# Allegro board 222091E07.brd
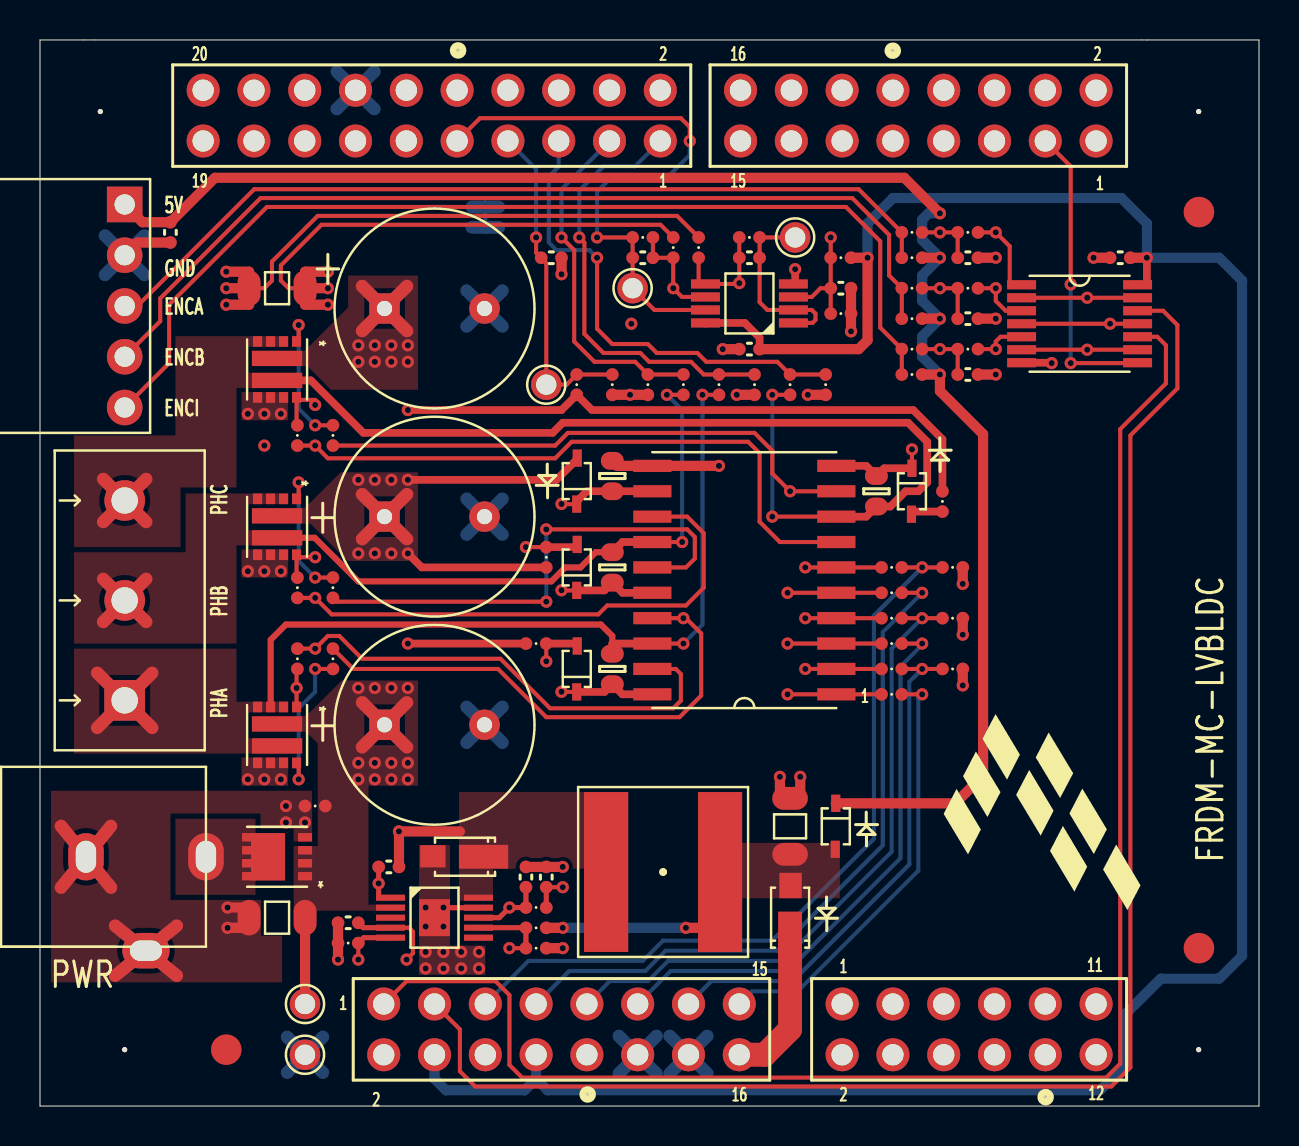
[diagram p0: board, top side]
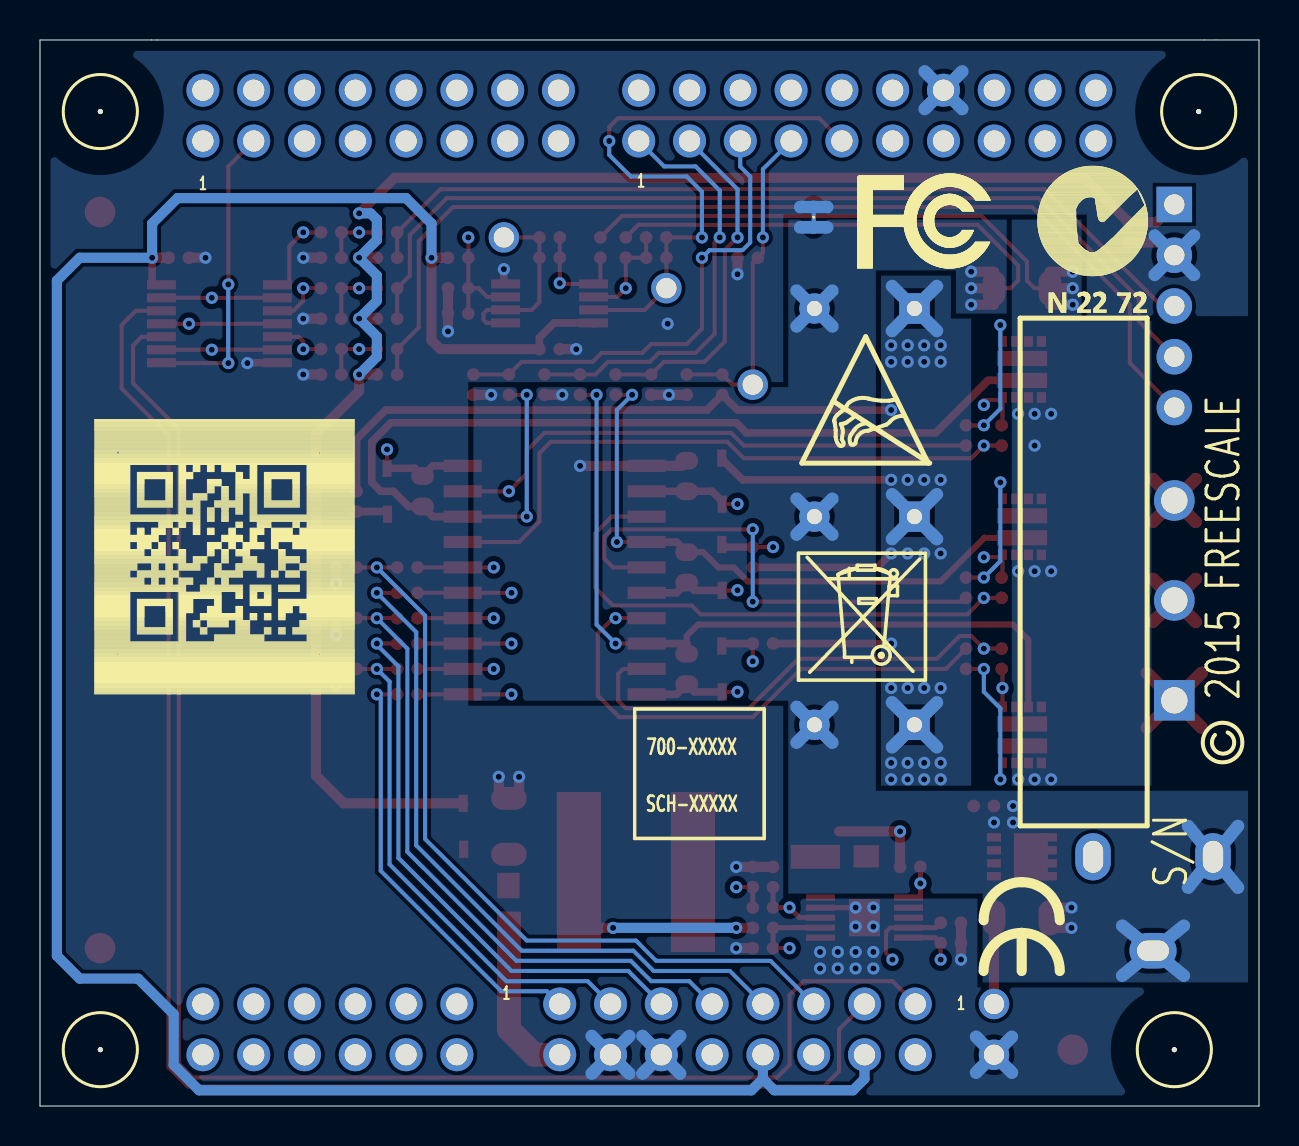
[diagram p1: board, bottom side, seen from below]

Outline 60.96 x 53.34 mm; copper layers: TOP, BOTTOM. Coordinates in mm from the lower left corner of the outline.
Outline path: 0,53.34 60.96,53.34 60.96,0 0,0 0,53.34

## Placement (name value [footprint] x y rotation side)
C1  220uF  [CAPRD_10X12P5MM]  19.73 19.08 0 top
C2  220uF  [CAPRD_10X12P5MM]  19.73 29.49 0 top
C3  220uF  [CAPRD_10X12P5MM]  19.73 39.9 0 top
C4  0.1uF  [CC0603_OV]  28.62 21.87 90 top
C5  0.1uF  [CC0603_OV]  28.62 26.95 90 top
C6  0.1uF  [CC0603_OV]  41.83 30.76 270 top
C10  0.1uF  [CC0603_OV]  28.62 31.52 90 top
C16  0.1uF  [CC0402_25]  40.05 40.92 0 top
C17  0.1uF  [CC0402_25]  25.57 42.44 0 top
C18  0.1uF  [CC0402_25]  35.48 37.87 180 top
C22  0.01uF  [CC0402_25]  35.48 42.44 180 top
C23  0.01uF  [CC0402_25]  30.14 42.44 180 top
C24  100pF  [CC0402_25]  46.4 42.44 0 top
C25  100pF  [CC0402_25]  46.4 39.4 0 top
C26  100pF  [CC0402_25]  46.4 36.6 0 top
C27  0.1uF  [CC0402_25]  6.52 43.71 270 top
C29  0.1uF  [CC0402_25]  54.02 42.44 180 top
C35  0.1uF  [CC0402_25]  17.44 11.96 0 top
C36  6.8nF  [CC0402_25]  15.41 9.17 180 top
C37  24pF  [CC0402_25]  24.3 11.46 90 top
C38  620pF  [CC0402_25]  25.32 11.46 90 top
C39  4.7uF  [CC1206_OV]  11.86 9.42 180 top
C40  47uF  [CC1206_OV]  37.51 14 90 top
D1  1N914  [SODFL2513X100N]  43.61 30.76 270 top
D2  1N914  [SODFL2513X100N]  26.84 26.95 90 top
D3  1N914  [SODFL2513X100N]  26.84 21.87 90 top
D4  1N914  [SODFL2513X100N]  26.84 31.27 90 top
D5  DFLS1100  [SODFL3718X100N]  21.25 12.47 180 top
D6  1N914  [SODFL2513X100N]  39.8 14 270 top
D7  DFLS1100  [SODFL3718X100N]  37.51 9.42 90 top
J1  SSQ-108-03-G-D  [SAMTEC_SSQ-108-03-G-D]  52.81 48.29 180 top
J2  SSQ-110-03-G-D  [SAMTEC_SSQ-110-03-G-D]  31.02 48.29 180 top
J3  SSQ-108-03-G-D  [SAMTEC_SSQ-108-03-G-D]  17.19 5.11 0 top
J4  SSQ-106-03-G-D  [SAMTEC_SSQ-106-03-G-D]  40.11 5.11 0 top
J6  PJ-102AH  [CON_PJ-102AH]  8.3 12.47 0 top
J7  KRM03  [CON_KRM03]  4.24 25.3 270 top
J8  22-05-3051  [CON_22-05-3051]  4.24 45.11 90 top
L1  47uH  [IND_SRN8040]  31.16 11.71 0 top
NOREF  -  []  55.04 9.8 90 top
NOREF#2  -  [unnamed#2]  57.96 44.73 0 top
NOREF#3  -  []  -43.63 -145.92 0 top
NOREF#4  -  []  182.19 53.34 0 top
NOREF#5  -  []  58.85 25.04 0 top
NOREF#6  -  []  -27.3 -36.7 0 top
NOREF#7  -  []  0 53.34 0 top
NOREF#8  -  []  -418.71 -339.88 0 top
NOREF#9  -  []  -392.68 185.27 0 top
NOREF#10  -  []  60.96 0 90 top
NOREF#11  -  [unnamed#2]  9.32 2.82 0 top
NOREF#12  -  []  4.24 2.82 0 top
NOREF#13  -  [unnamed#2]  57.96 7.9 0 top
NOREF#14  -  []  -15.5 14.61 180 bottom
NOREF#15  -  [unnamed#2]  3.02 49.76 180 bottom
NOREF#16  -  []  5.59 14.02 90 bottom
NOREF#17  -  [unnamed#2]  57.94 49.76 180 bottom
NOREF#18  -  []  11.87 9.36 180 bottom
NOREF#19  -  []  51.87 27.86 180 bottom
NOREF#20  -  [unnamed#2]  57.94 2.82 180 bottom
NOREF#21  -  []  23.03 21.31 180 bottom
NOREF#22  -  [unnamed#2]  4.24 2.82 180 bottom
NOREF#23  -  []  26.59 21.79 90 bottom
NOREF#24  -  []  1.95 18.31 90 bottom
Q1  FDMC8030  [POWER33-10]  11.86 18.57 270 top
Q2  FDMC8030  [POWER33-10]  11.86 28.98 270 top
Q3  FDMC8030  [POWER33-10]  11.86 36.86 270 top
Q4  FDMC6679AZ  [POWER33-8]  11.86 12.47 180 top
R1  10  [RC0402_25]  45.13 30.25 270 top
R2  10  [RC0402_25]  25.32 27.46 90 top
R3  10K  [RC0402_25]  13.76 15.01 180 top
R4  10  [RC0402_25]  12.87 22.38 270 top
R5  10  [RC0402_25]  14.65 25.93 90 top
R6  10  [RC0402_25]  14.65 33.55 90 top
R7  10  [RC0402_25]  24.81 23.14 0 top
R8  10  [RC0402_25]  14.65 22.38 270 top
R9  10  [RC0402_25]  12.87 25.93 90 top
R10  1K  [RC0402_25]  42.59 20.6 180 top
R11  1K  [RC0402_25]  42.59 21.87 180 top
R12  10  [RC0402_25]  12.87 33.55 90 top
R16  1K  [RC0402_25]  42.59 23.14 180 top
R17  1K  [RC0402_25]  42.59 24.41 180 top
R18  1K  [RC0402_25]  42.59 25.68 180 top
R19  1K  [RC0402_25]  42.59 26.95 180 top
R32  10K  [RC0402_25]  40.05 42.44 180 top
R33  10.7K  [RC0402_25]  26.84 36.09 90 top
R34  10K  [RC0402_25]  40.05 39.65 0 top
R35  3K  [RC0402_25]  28.62 36.09 270 top
R36  0.010  [RC1206_OV]  11.86 40.92 0 top
R37  1K  [RC0402_25]  32.94 42.95 270 top
R38  1K  [RC0402_25]  31.67 42.95 270 top
R39  20K  [RC0402_25]  30.14 43.46 180 top
R40  20K  [RC0402_25]  35.48 43.46 180 top
R41  10.7K  [RC0402_25]  32.18 36.09 90 top
R42  3K  [RC0402_25]  30.4 36.09 270 top
R43  3K  [RC0402_25]  35.73 36.09 270 top
R44  10.7K  [RC0402_25]  33.95 36.09 90 top
R45  3K  [RC0402_25]  39.29 36.09 270 top
R46  10.7K  [RC0402_25]  37.51 36.09 90 top
R47  2K  [RC0402_25]  46.4 43.71 0 top
R48  1K  [RC0402_25]  43.61 42.44 180 top
R49  100  [RC0402_25]  43.61 43.71 0 top
R50  2K  [RC0402_25]  46.4 40.92 0 top
R51  1K  [RC0402_25]  43.61 39.4 180 top
R52  100  [RC0402_25]  43.61 40.92 0 top
R53  1K  [RC0402_25]  43.61 36.6 180 top
R54  2K  [RC0402_25]  46.4 37.87 0 top
R55  100  [RC0402_25]  43.61 37.87 0 top
R56  84.5K  [RC0402_25]  15.41 8.15 180 top
R57  59K  [RC0402_25]  24.81 8.92 180 top
R58  10K  [RC0402_25]  24.81 7.9 0 top
R59  150K  [RC0402_25]  24.81 9.93 0 top
R70  4.7K  [RC0402_25]  45.64 21.87 0 top
R71  4.7K  [RC0402_25]  45.64 24.41 0 top
R72  4.7K  [RC0402_25]  45.64 26.95 0 top
SH1  0  [RC0402_25_CT]  22.27 44.48 270 bottom
TP4  TP  [TP_TH_040]  37.76 43.46 0 top
TP5  TP  [TP_TH_040]  25.32 36.09 0 top
TP6  TP  [TP_TH_040]  29.64 40.92 0 top
TP7  TP  [TP_TH_040]  13.25 5.11 0 top
TP8  TP  [TP_TH_040]  13.25 2.57 0 top
U1  FAN7888  [SOIC127P1032X265-20N]  35.22 26.31 180 top
U2  FAN4852  [SOP65P490X110-8N]  35.48 40.16 180 top
U6  74LVX14  [SOP65P640X120-14N]  51.99 39.14 0 top
U7  TPS54060  [SOP50P490X110-11N]  19.73 9.42 0 top

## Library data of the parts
C1-C3 = CAP_POL
C4-C6 C10 C16-C18 C22-C27 C29 C35-C40 = CAP_NP
D1-D4 D6 = 1N914BWS
D5 D7 = DFLS1100
J1 J3 = CONN_2x8
J2 = CONN_2x10
J4 = CONN_2x6
J6 = PJ-102AH
J7 = KRM03
J8 = CON5
L1 = SRN8040
Q1-Q3 = FDMC8030
Q4 = FDMC6679AZ
R1-R12 R16-R19 R32-R59 R70-R72 = RES
SH1 = SH_RES
TP4-TP8 = TP
U1 = FAN7888
U2 = FAN4852
U6 = 74LVX14
U7 = TPS54060

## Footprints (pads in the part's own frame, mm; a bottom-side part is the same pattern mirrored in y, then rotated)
CAPRD_10X12P5MM
  rect 1.524x1.524 hole 0.762: 1(-2.5,0)
  round 1.524 hole 0.762: 2(2.5,0)
CC0402_25
  round 0.635 smd: 1(-0.508,0) 2(0.508,0)
CC0603_OV
  oval 0.889x1.143 smd: 1(-0.762,0) 2(0.762,0)
CC1206_OV
  oval 1.143x1.778 smd: 1(-1.4,0) 2(1.4,0)
CON_22-05-3051
  rect 1.778x1.778 hole 1.016: 1(0,0)
  round 1.778 hole 1.016: 2(-2.54,0) 3(-5.08,0) 4(-7.62,0) 5(-10.16,0)
CON_KRM03
  rect 2.032x2.032 hole 1.321: 1(5,0)
  round 2.032 hole 1.321: 2(0,0) 3(-5,0)
CON_PJ-102AH
  oval 1.778x2.362 hole 1.016x1.6: 1(0,0) 2(-6,0)
  oval 2.362x1.778 hole 1.6x1.016: 3(-3,-4.7)
IND_SRN8040
  rect 2.21x8.001 smd: 1(-2.85,0) 2(2.85,0)
POWER33-8
  rect 1.7x2.37 smd: (0.45,0)
  rect 0.7x0.42 smd: 1(-1.4,0.975) 2(-1.4,0.325) 3(-1.4,-0.325) 4(-1.4,-0.975) 5(1.4,-0.975) 6(1.4,-0.325) 7(1.4,0.325) 8(1.4,0.975)
POWER33-10
  rect 0.533x0.457 smd: 1(-1.4,0.975) 2(-1.4,0.325) 3(-1.4,-0.325) 4(-1.4,-0.975) 5(1.4,-0.975) 6(1.4,-0.325) 7(1.4,0.325) 8(1.4,0.975)
  rect 0.762x2.515 smd: 9(-0.55,0) 10(0.55,0)
RC0402_25
  round 0.635 smd: 1(-0.508,0) 2(0.508,0)
RC0402_25_CT
  round 0.635 smd: 1(-0.508,0) 2(0.508,0)
RC1206_OV
  oval 1.143x1.778 smd: 1(-1.4,0) 2(1.4,0)
SAMTEC_SSQ-106-03-G-D
  round 1.651 hole 1.067: 1(0,0) 2(0,-2.54) 3(2.54,0) 4(2.54,-2.54) 5(5.08,0) 6(5.08,-2.54) 7(7.62,0) 8(7.62,-2.54) 9(10.16,0) 10(10.16,-2.54) 11(12.7,0) 12(12.7,-2.54)
SAMTEC_SSQ-108-03-G-D
  round 1.651 hole 1.067: 1(0,0) 2(0,-2.54) 3(2.54,0) 4(2.54,-2.54) 5(5.08,0) 6(5.08,-2.54) 7(7.62,0) 8(7.62,-2.54) 9(10.16,0) 10(10.16,-2.54) 11(12.7,0) 12(12.7,-2.54) 13(15.24,0) 14(15.24,-2.54) 15(17.78,0) 16(17.78,-2.54)
SAMTEC_SSQ-110-03-G-D
  round 1.651 hole 1.067: 1(0,0) 2(0,-2.54) 3(2.54,0) 4(2.54,-2.54) 5(5.08,0) 6(5.08,-2.54) 7(7.62,0) 8(7.62,-2.54) 9(10.16,0) 10(10.16,-2.54) 11(12.7,0) 12(12.7,-2.54) 13(15.24,0) 14(15.24,-2.54) 15(17.78,0) 16(17.78,-2.54) 17(20.32,0) 18(20.32,-2.54) 19(22.86,0) 20(22.86,-2.54)
SODFL2513X100N
  rect 0.864x0.457 smd: A(1.15,-0.025) C(-1.15,0)
SODFL3718X100N
  rect 1.27x1.118 smd: A(1.61,-0.025)
  rect 2.464x1.194 smd: C(-0.93,0)
SOIC127P1032X265-20N
  rect 1.905x0.61 smd: 1(-4.6,5.715) 2(-4.6,4.445) 3(-4.6,3.175) 4(-4.6,1.905) 5(-4.6,0.635) 6(-4.6,-0.635) 7(-4.6,-1.905) 8(-4.6,-3.175) 9(-4.6,-4.445) 10(-4.6,-5.715) 11(4.6,-5.715) 12(4.6,-4.445) 13(4.6,-3.175) 14(4.6,-1.905) 15(4.6,-0.635) 16(4.6,0.635) 17(4.6,1.905) 18(4.6,3.175) 19(4.6,4.445) 20(4.6,5.715)
SOP50P490X110-11N
  rect 1.448x0.305 smd: 1(-2.2,1) 2(-2.2,0.5) 3(-2.2,0) 4(-2.2,-0.5) 5(-2.2,-1) 6(2.2,-1) 7(2.2,-0.5) 8(2.2,0) 9(2.2,0.5) 10(2.2,1)
  rect 1.549x1.854 smd: 11(0,0)
SOP65P490X110-8N
  rect 1.448x0.457 smd: 1(-2.2,0.975) 2(-2.2,0.325) 3(-2.2,-0.325) 4(-2.2,-0.975) 5(2.2,-0.975) 6(2.2,-0.325) 7(2.2,0.325) 8(2.2,0.975)
SOP65P640X120-14N
  rect 1.448x0.457 smd: 1(-2.9,1.95) 2(-2.9,1.3) 3(-2.9,0.65) 4(-2.9,0) 5(-2.9,-0.65) 6(-2.9,-1.3) 7(-2.9,-1.95) 8(2.9,-1.95) 9(2.9,-1.3) 10(2.9,-0.65) 11(2.9,0) 12(2.9,0.65) 13(2.9,1.3) 14(2.9,1.95)
TP_TH_040
  round 1.524 hole 1.016: 1(0,0)
unnamed#2
  round 1.524 smd: (0,0)

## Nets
3V3: C18.1 C29.1 J3.4(B2) J3.8(B4) R32.1 U2.8(V+) U6.14(VCC)
5V: C27.1 D6.C J8.1 R48.1 R51.1 R53.1
5V5: C40.1 D6.A D7.A L1.2 R57.1
5V_OUT: D7.C J3.16(B8)
GND: C16.2 C17.2 C18.2 C24.2 C25.2 C26.2 C27.2 C29.2 C36.2 C37.2 C38.2 C40.2 D5.A J2.14(B7) J3.12(B6) J3.14(B7) J8.2 R34.2 R56.2 R58.2 R70.2 R71.2 R72.2 SH1.1 TP8.1(TP) U2.4(-IN) U6.7(GND) U7.9(GND) U7.11(PAD)
GNDM: C1.2(MINUS) C2.2(MINUS) C3.2(MINUS) C10.2 C39.2 J6.2 J6.3 Q4.4(G) R3.2 R35.2 R36.2 R38.1 R42.2 R43.2 R45.2 SH1.2 U1.11(GND)
ADC_MID: C22.1 R40.1 TP4.1(TP) U2.1(OUTA) U2.2(-INA)
BEMF_A: J2.1(A1) R43.1 R44.2
BEMF_B: J2.3(A2) R41.2 R42.1
BEMF_C: J2.5(A3) R45.1 R46.2
CS_DCB_H: Q1.5(S13) Q1.6(S12) Q1.7(S11) Q2.5(S13) Q2.6(S12) Q2.7(S11) Q3.5(S13) Q3.6(S12) Q3.7(S11) R36.1 R37.1
CUR_DCB: C23.2 J2.9(A5) R39.2 TP6.1(TP) U2.7(OUTB)
ENC_A: J3.3(A2) U6.12(Y)
ENC_B: J3.1(A1) U6.10(Y)
ENC_I: J1.3(A2) U6.8(Y)
HOA: R4.1 U1.19(HO1)
HOB: R5.1 U1.15(HO2)
HOC: R6.1 U1.9(HO3)
LOA: R8.1 U1.17(LO1)
LOB: R9.1 U1.13(LO2)
LOC: R12.1 U1.7(LO3)
PH_A: C4.2 J7.1 Q1.2(S11) Q1.3(S12) Q1.4(S13) Q1.10(D2) R44.1 U1.18(VS1)
PH_B: C5.2 J7.2 Q2.2(S11) Q2.3(S12) Q2.4(S13) Q2.10(D2) R41.1 U1.14(VS2)
PH_C: C6.2 J7.3 Q3.2(S11) Q3.3(S12) Q3.4(S13) Q3.10(D2) R46.1 U1.8(VS3)
PWM_AB: J3.13(A7) R11.1 R70.1
PWM_AT: J3.15(A8) R10.1
PWM_BB: J3.9(A5) R17.1 R71.1
PWM_BT: J3.11(A6) R16.1
PWM_CB: J3.5(A3) R19.1 R72.1
PWM_CT: J3.7(A4) R18.1
VM: C1.1(PLUS) C2.1(PLUS) C3.1(PLUS) C39.1 D4.A Q1.9(D2) Q2.9(D2) Q3.9(D2) Q4.1(S1) Q4.2(S2) Q4.3(S3) R1.1 R2.1 R3.1 R7.1 R33.1 TP7.1(TP) U7.2(VIN)
VOLT_DCB: C17.1 J2.7(A4) R33.2 R35.1 TP5.1(TP)
N24033468: C4.1 D3.C U1.20(VB1)
N24033594: C5.1 D2.C U1.16(VB2)
N24033653: C6.1 D1.C U1.10(VB3)
N24035180: D1.A R1.2
N24035201: D2.A R2.2
N24035206: D3.A R7.2
N24035227: Q1.1(G2) R4.2
N24035245: Q1.8(G2) R8.2
N24035263: Q2.1(G2) R5.2
N24035281: Q2.8(G2) R9.2
N24035326: Q3.8(G2) R12.2
N24035327: Q3.1(G2) R6.2
N24037051: C10.1 D4.C U1.12(VDD)
N24055425: C16.1 R32.2 R34.1 U2.3(+INA)
N24056935: R18.2 U1.5(HIN3)
N24056936: R16.2 U1.3(HIN2)
N24056937: R10.2 U1.1(HIN1)
N24056938: R19.2 U1.6(LIN3)
N24056939: R17.2 U1.4(LIN2)
N24056940: R11.2 U1.2(LIN1)
N24071789: C22.2 R37.2 R40.2 U2.5(+INB)
N24071791: C23.1 R38.2 R39.1 U2.6(-INB)
N24077170: C24.1 R47.1 R49.2
N24077180: J8.3 R48.2 R49.1
N24077887: J8.4 R51.2 R52.1
N24077889: C25.1 R50.1 R52.2
N24077981: J8.5 R53.2 R55.1
N24077985: C26.1 R54.1 R55.2
N24130653: R47.2 U6.1(A)
N24130655: R50.2 U6.3(A)
N24130657: R54.2 U6.5(A)
N24130659: U6.6(Y) U6.9(A)
N24130661: U6.4(Y) U6.11(A)
N24130663: U6.2(Y) U6.13(A)
N24141092: J6.1 Q4.5(D1) Q4.6(D2) Q4.7(D3) Q4.8(D4)
N24147614: C35.1 U7.1(BOOT)
N24147651: C35.2 D5.C L1.1 U7.10(PH)
N24147683: R57.2 R58.1 U7.7(VSEN)
N24147707: R56.1 U7.5(RT)
N24147711: C36.1 U7.4(SS)
N24147721: C37.1 R59.1 U7.8(COMP)
N24147753: C38.1 R59.2

Pads without a net: J1 1 2 4 5 6 7 8 9 10 11 12 13 14 15 16; J2 2 4 6 8 10 11 12 13 15 16 17 18 19 20; J3 2 6 10; J4 1 2 3 4 5 6 7 8 9 10 11 12; U7 3 6

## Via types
v1: diameter 0.61, hole 0.305, TOP to BOTTOM, 160 vias

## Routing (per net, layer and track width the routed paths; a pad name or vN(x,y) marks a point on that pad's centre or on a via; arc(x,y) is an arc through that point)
3V3: length 122.1
  TOP w0.381: U6.14 55.35,41.09 v1(55.35,42.44) ; 33.28,39.14 U2.8 35.25,39.18 35.99,38.44 C18.1
  TOP w0.508: C18.1 40.94,37.87 41.38,38.32 v1(41.38,42.44) R32.1 ; C29.1 v1(55.35,42.44)
  BOTTOM w0.508: 24.81,1.36 J3.8 ; 24.81,1.36 24.24,0.79 20.3,0.79 19.73,1.36 J3.4 ; 24.81,1.36 25.38,0.79 53,0.79 54.27,2.06 54.27,4.6 56.05,6.38 58.97,6.38 60.12,7.52 60.12,41.3 58.97,42.44 v1(55.35,42.44) 55.35,44.16 54.08,45.43 42.65,45.43 41.38,44.16 v1(41.38,42.44)
5V: length 85
  TOP w0.508: v1(45,44.67) 43.22,46.44 8.74,46.44 C27.1 5.12,44.22 J8.1 ; R51.1 v1(45,39.4) ; R53.1 v1(45,36.6) 45,35.78 47.16,33.62 47.16,16.54 45.77,15.15 D6.C ; R48.1 v1(45,42.44)
  BOTTOM w0.508: v1(45,36.6) 44.11,37.49 44.11,38.51 v1(45,39.4) 44.11,40.28 44.11,41.55 v1(45,42.44) 44.11,43.33 44.11,44.35 44.43,44.67 v1(45,44.67)
5V5: length 11.5
  TOP w0.508: L1.2 34.01,8.92 v1(32.3,8.92) ; R57.1 v1(26.14,8.92)
  BOTTOM w0.508: v1(26.14,8.92) v1(32.3,8.92)
5V_OUT: length 7.7
  TOP w1.194: J3.16 36.24,2.57 37.51,3.84 D7.C
GND: length 52
  TOP w0.254: U7.9 20.18,9.92 v1(20.17,9.93)
  TOP w0.381: U6.7 50.57,37.19 v1(50.59,37.17) ; v1(37.76,41.87) 37.76,41.13 U2.4
  TOP w0.508: C26.2 v1(47.8,36.6) ; C16.2 R34.2 v1(40.56,38.76) ; C36.2 R56.2 v1(14.9,7.33) ; v1(38.02,16.47) 38.02,15.4 C40.2 37,15.4 v1(37,16.47) ; C25.2 v1(47.8,39.4) ; v1(26.14,11.96) C38.2 C37.2 ; C18.2 v1(34.14,37.87) ; R71.2 v1(46.15,23.58) ; C27.2 4.87,43.21 J8.2 ; C17.2 v1(26.08,41.62) ; R58.2 v1(26.14,7.9) ; C24.2 v1(47.8,42.44) ; R70.2 v1(46.15,21.04) ; R72.2 v1(46.15,26.12) ; C29.2 v1(52.69,42.44)
  BOTTOM w0.635: J3.14 33.37,3.5 ; J3.14 31.49,3.5 ; J3.14 31.49,1.63 ; J3.14 33.37,1.63 ; 14.84,51.76 J2.14 ; J2.14 14.84,49.89 ; J2.14 16.72,49.89 ; J2.14 16.72,51.76 ; J3.12 30.83,3.5 ; J3.12 30.83,1.63 ; J3.12 28.95,1.63 ; J3.12 28.95,3.5 ; TP8.1 14.14,1.67 ; TP8.1 12.36,1.67 ; TP8.1 14.14,3.46 ; TP8.1 12.36,3.46 ; 3.25,43.55 J8.2 ; J8.2 5.22,43.55 ; J8.2 5.22,41.59 ; J8.2 3.25,41.59 ; 22.94,44.98 SH1.1 21.6,44.98
  vias: v1(19.28,9.93) v1(19.28,8.98) v1(19.28,7.71) v1(19.28,6.88) v1(20.17,8.98) v1(20.17,7.71) v1(20.17,6.88) v1(21.06,7.71) v1(21.06,6.88) v1(21.95,7.71) v1(21.95,6.88) v1(29.57,39.14)
GNDM: length 88.2
  TOP w0.203: R38.1 31.03,44.09 14.08,44.09 12.05,42.06 12.05,41.3 12.43,40.92 R36.2
  TOP w0.508: R36.2 13.26,41.74 v1(14.4,41.74) ; R36.2 13.26,40.09 v1(14.4,40.09) ; R36.2 v1(14.4,40.92) ; v1(33.95,32.03) U1.11 28.87,32.03 C10.2 ; v1(9.38,9.93) 10.46,9.93 C39.2 10.46,8.92 v1(9.38,8.92) ; R35.2 v1(29.51,35.59) R42.2 ; R43.2 v1(34.84,35.59) ; R45.2 v1(38.4,35.59)
  TOP w0.635: 1.05,14.01 J6.2 ; J6.2 3.54,10.93 ; J6.2 1.05,10.93 ; J6.2 3.54,14.01 ; J6.3 6.84,6.53 ; J6.3 3.76,6.53 ; J6.3 3.76,9.02 ; J6.3 6.84,9.02
  BOTTOM w0.635: J6.2 3.54,14.01 ; J6.2 1.05,14.01 ; J6.2 3.54,10.93 ; J6.2 1.05,10.93 ; C3.2 23.12,40.8 ; C3.2 21.34,40.8 ; C3.2 21.34,39.01 ; C3.2 23.12,39.01 ; C1.2 23.12,18.18 ; C1.2 23.12,19.97 ; C1.2 21.34,18.18 ; C1.2 21.34,19.97 ; 21.34,30.38 C2.2 ; C2.2 23.12,28.6 ; C2.2 21.34,28.6 ; C2.2 23.12,30.38 ; 22.94,43.97 SH1.2 21.6,43.97 ; 3.76,6.53 J6.3 ; J6.3 3.76,9.02 ; J6.3 6.84,6.53 ; J6.3 6.84,9.02
  vias: v1(12.3,15.01) v1(12.3,14.19) v1(13.25,14.19)
ADC_MID: length 9.5
  TOP w0.203: U2.1 38.63,39.18 38.78,39.33 38.78,39.65 38.6,39.83 U2.2 36.37,39.83 35.99,40.22 C22.1 R40.1 TP4.1
BEMF_A: length 21.7
  TOP w0.203: v1(26.97,43.46) 27.22,43.21 27.22,38.63 28.17,37.68 30.02,37.68 30.46,37.24 32.56,37.24 33.19,36.6 R44.2 R43.1
  BOTTOM w0.203: v1(26.97,43.46) 26.97,45.81 28.17,47.02 29.75,47.02 J2.1
BEMF_B: length 17.4
  TOP w0.203: v1(26.08,43.46) 26.71,42.82 26.71,38.25 27.73,37.24 29.76,37.24 R42.1 R41.2
  BOTTOM w0.203: J2.3 28.48,48.27 26.08,45.87 v1(26.08,43.46)
BEMF_C: length 23.9
  TOP w0.203: R45.1 R46.2 36.87,37.24 33.32,37.24 32.87,37.68 30.84,37.68 30.4,38.13 28.62,38.13 27.86,38.89 v1(27.86,42.44)
  BOTTOM w0.203: J2.5 25.94,47 25.44,46.51 25.44,43.21 25.83,42.82 27.48,42.82 v1(27.86,42.44)
CS_DCB_H: length 30.1
  TOP w0.203: R36.1 11.22,40.92 11.6,41.3 11.6,42.25 13.89,44.54 31.86,44.54 R37.1
  TOP w0.508: v1(9.32,41.74) 10.46,41.74 R36.1 ; R36.1 v1(9.32,40.92) ; R36.1 10.46,40.09 v1(9.32,40.09)
  vias: v1(10.39,34.63) v1(10.39,26.76) v1(10.39,16.34) v1(11.22,34.63) v1(11.22,33.05) v1(11.22,26.76) v1(11.22,16.34) v1(12.05,34.63) v1(12.05,26.76) v1(12.05,16.34)
CUR_DCB: length 29.8
  TOP w0.203: v1(32.49,48.29) 32.49,48.98 32.05,49.43 22,49.43 J2.9 ; v1(27.86,43.46) R39.2 C23.2 TP6.1 30.72,39.83 U2.7
  BOTTOM w0.203: v1(27.86,43.46) 27.86,45.75 28.62,46.51 31.41,46.51 32.49,47.59 v1(32.49,48.29)
ENC_A: length 78.5
  TOP w0.203: J3.3 21,3.84 21,1.74 21.76,0.98 53.57,0.98 54.53,1.93 54.53,33.55 56.88,35.9 56.88,39.08 56.16,39.79 U6.12
ENC_B: length 80.1
  TOP w0.203: U6.10 55.88,38.49 56.31,38.06 56.31,36.16 54.02,33.87 54.02,2.12 53.32,1.42 24.11,1.42 23.48,2.06 23.48,5.55 22.78,6.25 18.33,6.25 J3.1
ENC_I: length 15
  TOP w0.203: v1(51.54,41.11) 51.54,47.02 J1.3 ; v1(51.54,37.17) 54.87,37.17 U6.8
  BOTTOM w0.203: v1(51.54,41.11) v1(51.54,37.17)
HOA: length 24
  TOP w0.203: U1.19 31.79,21.87 32.05,21.62 32.05,20.28 31.67,19.9 25.51,19.9 23.03,22.38 16.11,22.38 14.97,23.52 14.4,23.52 v1(13.76,22.89) R4.1
HOB: length 25.3
  TOP w0.203: v1(25.32,25.23) 14.84,25.23 R5.1 ; v1(25.32,28.85) 32.37,28.85 32.75,28.47 32.75,27.39 32.3,26.95 U1.15
  BOTTOM w0.203: v1(25.32,28.85) v1(25.32,25.23)
HOC: length 27.3
  TOP w0.203: R6.1 25.76,33.05 26.4,33.68 35.73,33.68 36.62,32.79 36.62,31.65 v1(37.51,30.76) U1.9
LOA: length 26.2
  TOP w0.203: U1.17 v1(32.18,24.41) 32.3,24.41 33.06,23.65 33.06,20.54 31.98,19.46 25.32,19.46 22.9,21.87 15.67,21.87 R8.1
LOB: length 26.9
  TOP w0.203: U1.13 32.37,29.49 33.19,28.66 33.19,25.93 32.3,25.04 28.37,25.04 27.92,24.6 14.59,24.6 v1(13.76,25.43) R9.1
LOC: length 31.6
  TOP w0.203: U1.7 37,28.22 35.99,29.24 35.99,32.66 35.41,33.24 26.59,33.24 25.76,32.41 14.4,32.41 v1(13.76,33.05) R12.1
PH_A: length 46.9
  TOP w0.203: U1.18 v1(32.18,23.14) ; R44.1 v1(33.13,35.59)
  TOP w0.305: 11.54,19.98 11.54,23.33 12.3,24.09 28.05,24.09 28.62,23.52 28.62,23.14
  TOP w0.381: 11.54,19.98 Q1.3 ; C4.2 28.62,23.14 U1.18
  TOP w0.635: 2.86,21.67 J7.1 ; J7.1 2.86,18.93 ; J7.1 5.61,18.93 ; J7.1 5.61,21.67
  BOTTOM w0.203: v1(32.18,23.14) 33.13,24.09 v1(33.13,35.59)
PH_B: length 36.5
  TOP w0.203: R41.1 v1(31.35,35.59) ; U1.14 v1(32.11,28.22)
  TOP w0.305: Q2.10 13.74,28.43 15.92,26.25 25.57,26.25 26.27,26.95 27.03,26.95 27.79,27.71 C5.2
  TOP w0.381: U1.14 29.13,28.22 C5.2
  TOP w0.635: J7.2 5.31,24.23 ; J7.2 3.16,26.37 ; J7.2 3.16,24.23 ; J7.2 5.31,26.37
  BOTTOM w0.203: v1(32.11,28.22) 32.11,34.82 v1(31.35,35.59)
PH_C: length 57.7
  TOP w0.203: v1(36.62,29.49) U1.8 ; R46.1 v1(36.62,35.59)
  TOP w0.381: U1.8 41.32,29.49 C6.2 42.53,30 43.29,30.76 43.92,30.76 44.37,31.2 44.37,33.24 43.41,34.19 26.14,34.19 25.63,33.68 16.17,33.68 13.55,36.31 Q3.10
  TOP w0.635: J7.3 5.31,31.37 ; J7.3 3.16,29.23 ; J7.3 3.16,31.37 ; J7.3 5.31,29.23
  BOTTOM w0.203: v1(36.62,29.49) v1(36.62,35.59)
PWM_AB: length 26
  TOP w0.203: R11.1 v1(44.11,21.87) R70.1
  BOTTOM w0.203: J3.13 33.57,6.25 37.64,6.25 43.48,12.09 43.48,21.23 v1(44.11,21.87)
PWM_AT: length 21.6
  TOP w0.203: R10.1 v1(44.11,20.6)
  BOTTOM w0.203: J3.15 35.6,5.74 37.89,5.74 43.92,11.77 43.92,20.41 v1(44.11,20.6)
PWM_BB: length 32.7
  TOP w0.203: R71.1 v1(44.11,24.41) R17.1
  BOTTOM w0.203: J3.9 28.49,6.25 30.4,6.25 31.41,7.26 37.13,7.26 42.59,12.73 42.59,22.89 v1(44.11,24.41)
PWM_BT: length 28.4
  TOP w0.203: R16.1 v1(44.11,23.14)
  BOTTOM w0.203: v1(44.11,23.14) 44.11,23.08 43.03,22 43.03,12.41 37.38,6.76 31.54,6.76 J3.11
PWM_CB: length 39.5
  TOP w0.203: R72.1 v1(44.11,26.95) R19.1
  BOTTOM w0.203: J3.5 24.43,7.26 30.14,7.26 31.16,8.28 36.62,8.28 41.7,13.36 41.7,24.54 v1(44.11,26.95)
PWM_CT: length 35.1
  TOP w0.203: R18.1 v1(44.11,25.68)
  BOTTOM w0.203: v1(44.11,25.68) 42.14,23.71 42.14,13.04 36.87,7.77 31.29,7.77 30.27,6.76 26.46,6.76 J3.7
VM: length 94.9
  TOP w0.381: v1(18.4,34.82) 26.08,34.82 R33.1 27.6,34.82 43.67,34.82 45.13,33.36 R1.1 ; R2.1 19.09,26.95 v1(18.4,27.65) ; R7.1 v1(18.4,23.14) ; v1(18.4,31.33) 25.83,31.33 26.87,32.37 D4.A
  TOP w0.508: C39.1 13.26,5.11 TP7.1
  TOP w0.635: 16.11,28.37 C2.1 ; C2.1 16.11,30.61 ; C2.1 18.35,30.61 ; C2.1 18.35,28.37 ; C1.1 18.35,20.19 ; C1.1 16.11,20.19 ; C1.1 18.35,17.96 ; C1.1 16.11,17.96 ; C3.1 18.35,38.79 ; C3.1 18.35,41.02 ; C3.1 16.11,38.79 ; C3.1 16.11,41.02
  BOTTOM w0.635: 16.11,38.79 C3.1 ; C3.1 16.11,41.02 ; C3.1 18.35,41.02 ; C3.1 18.35,38.79 ; C1.1 18.35,17.96 ; C1.1 16.11,20.19 ; C1.1 16.11,17.96 ; C1.1 18.35,20.19 ; 16.11,30.61 C2.1 ; C2.1 18.35,30.61 ; C2.1 18.35,28.37 ; C2.1 16.11,28.37
  vias: v1(15.92,38.06) v1(15.92,37.24) v1(15.92,31.33) v1(15.92,27.65) v1(15.92,20.92) v1(15.92,17.17) v1(15.92,16.34) v1(16.74,38.06) v1(16.74,37.24) v1(16.74,31.33) v1(16.74,27.65) v1(16.74,20.92) v1(16.74,17.17) v1(16.74,16.34) v1(17.57,38.06) v1(17.57,37.24) v1(17.57,31.33) v1(17.57,27.65) v1(17.57,20.92) v1(17.57,17.17) v1(17.57,16.34) v1(18.4,38.06) v1(18.4,37.24) v1(18.4,20.92) v1(18.4,17.17) v1(18.4,16.34)
VOLT_DCB: length 16.5
  TOP w0.203: R35.1 R33.2 26.33,36.09 TP5.1 25.32,42.19 C17.1 24.81,42.7 v1(24.81,43.46)
  BOTTOM w0.203: J2.7 24.81,46.88 v1(24.81,43.46)
N24033468: length 4.9
  TOP w0.203: v1(26.08,20.73) 26.09,20.72 D3.C
  TOP w0.381: D3.C 28.23,20.72 C4.1 29.13,20.6 U1.20
N24033594: length 4.9
  TOP w0.203: v1(26.08,25.81) 26.09,25.8 D2.C
  TOP w0.381: D2.C 28.23,25.8 C5.1 29.13,25.68 U1.16
N24033653: length 5.1
  TOP w0.203: D1.C v1(43.61,32.85)
  TOP w0.381: D1.C 42.22,31.91 C6.1 41.32,32.03 U1.10
N24035180: length 1.7
  TOP w0.381: D1.A 43.58,29.74 R1.2
N24035201: length 2.7
  TOP w0.203: R2.2 v1(24.3,27.97)
  TOP w0.381: R2.2 26.87,27.97 D2.A
N24035206: length 2.6
  TOP w0.203: R7.2 v1(25.32,22.25)
  TOP w0.381: D3.A 26.87,23.14 R7.2
N24035227: length 1.9
  TOP w0.203: R4.2 12.83,21.87 v1(12.83,20.92) Q1.1
N24035245: length 7.7
  TOP w0.203: v1(12.93,16.34) 12.93,17.17 Q1.8 ; v1(13.76,21.87) R8.2
  BOTTOM w0.203: v1(13.76,21.87) 13.76,20.73 12.93,19.9 v1(12.93,16.34)
N24035263: length 6.9
  TOP w0.203: v1(12.93,31.2) 12.93,30.38 Q2.1 ; v1(13.76,26.44) R5.2
  BOTTOM w0.203: v1(12.93,31.2) 12.93,27.27 v1(13.76,26.44)
N24035281: length 2.1
  TOP w0.203: R9.2 12.83,26.44 12.83,27.46 ; v1(13.76,27.46) 12.83,27.46 ; 12.83,27.46 Q2.8
N24035326: length 2.6
  TOP w0.203: R12.2 12.83,34.06 12.83,35.33 ; Q3.8 12.83,35.33 ; 12.83,35.33 13.76,35.33 v1(13.76,35.08)
N24035327: length 7.2
  TOP w0.203: v1(12.93,39.08) 12.93,38.26 Q3.1 ; v1(13.76,34.06) R6.2
  BOTTOM w0.203: v1(12.93,39.08) 12.93,34.89 v1(13.76,34.06)
N24037051: length 4.9
  TOP w0.203: D4.C 26.09,30.12 v1(26.08,30.12)
  TOP w0.381: U1.12 C10.1 27.35,30.76 26.84,30.25 D4.C
N24055425: length 5.9
  TOP w0.203: v1(39.54,43.46) R32.2 C16.1 ; C16.1 39.03,40.92 38.6,40.48 U2.3 ; C16.1 R34.1
N24056935: length 4.7
  TOP w0.203: v1(37.38,25.68) U1.5 R18.2
N24056936: length 4.7
  TOP w0.203: v1(37.38,23.14) U1.3 R16.2
N24056937: length 4.7
  TOP w0.203: R10.2 U1.1 v1(37.38,20.6)
N24056938: length 3.8
  TOP w0.203: R19.2 U1.6 v1(38.27,26.95)
N24056939: length 3.8
  TOP w0.203: R17.2 U1.4 v1(38.27,24.41)
N24056940: length 3.8
  TOP w0.203: v1(38.27,21.87) U1.2 R11.2
N24071789: length 5.7
  TOP w0.203: R37.2 32.94,41.13 U2.5 34.97,41.13 v1(34.97,41.17) C22.2 R40.2
N24071791: length 5.3
  TOP w0.203: U2.6 32.1,40.48 v1(31.67,40.92) R38.2 C23.1 R39.1
N24077170: length 3
  TOP w0.203: C24.1 R47.1 v1(45,43.71) R49.2
N24077180: length 43.4
  TOP w0.203: R48.2 R49.1 40.94,45.87 10.71,45.87 4.87,40.03 J8.3
N24077887: length 47.4
  TOP w0.203: J8.4 6.01,39.27 6.01,40.41 11.03,45.43 40.62,45.43 42.46,43.59 42.46,41.55 R52.1 R51.2
N24077889: length 3.3
  TOP w0.203: C25.1 R50.1 v1(45,40.92) R52.2
N24077981: length 51.5
  TOP w0.203: R53.2 R55.1 42.02,38.95 42.02,43.27 40.3,44.98 11.35,44.98 6.46,40.09 6.46,37.17 J8.5
N24077985: length 3
  TOP w0.203: R55.2 v1(45,37.87) R54.1 C26.1
N24130653: length 4.4
  TOP w0.203: U6.1 48.49,41.09 48.49,43.01 v1(47.8,43.71) R47.2
N24130655: length 3
  TOP w0.203: U6.3 48.29,39.79 47.8,40.28 v1(47.8,40.92) R50.2
N24130657: length 2.7
  TOP w0.203: U6.5 48.04,38.49 47.8,38.25 v1(47.8,37.87) R54.2
N24130659: length 5.8
  TOP w0.203: U6.6 v1(52.37,37.84) U6.9
N24130661: length 5.8
  TOP w0.203: U6.11 v1(53.51,39.14) U6.4
N24130663: length 5.8
  TOP w0.203: U6.2 v1(52.37,40.44) U6.13
N24147614: length 2.1
  TOP w0.254: C35.1 v1(16.94,11.14) 16.94,10.42 U7.1
N24147651: length 4.8
  TOP w0.508: 21,13.74 v1(17.95,13.74) C35.2
N24147683: length 4.2
  TOP w0.203: R58.1 v1(23.48,7.9)
  TOP w0.254: R58.1 R57.2 24.29,8.92 U7.7
N24147707: length 2.5
  TOP w0.203: R56.1 v1(15.92,7.33)
  TOP w0.254: U7.5 16.19,8.42 R56.1
N24147711: length 4.4
  TOP w0.203: v1(18.33,7.33) 18.65,7.65 18.65,8.72 18.45,8.92 U7.4
  TOP w0.254: C36.1 16.17,8.92 U7.4
N24147721: length 3.6
  TOP w0.254: C37.1 R59.1 v1(23.48,9.93) 22.97,9.42 U7.8
N24147753: length 1.8
  TOP w0.203: C38.1 v1(26.14,10.95)
  TOP w0.254: C38.1 R59.2

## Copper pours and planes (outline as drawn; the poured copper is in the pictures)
5V5 on TOP: 40,10.4 32.9,10.4 32.9,13.17 40,13.17
GND on TOP: 18.95,13.06 20.5,13.06 20.5,8.03 22.27,8.03 22.27,6.57 18.95,6.57
GND on BOTTOM: 39.54,20.03 39.54,36.22 23.79,36.22 23.79,44.6 8.62,44.6 8.62,39.52 0.55,39.52 0.55,52.79 60.43,52.79 60.43,0.53 2.65,0.53 2.65,5.93 14.08,5.93 14.08,10.38 23.79,10.38 23.79,20.03
GNDM on TOP: 12.68,13.24 12.68,13.88 11.03,13.88 11.03,14.63 6.52,14.63 6.52,10.31 12.11,10.31 12.11,6.18 0.55,6.18 0.55,15.77 13.61,15.77 13.61,13.24
GNDM on BOTTOM: 39.29,20.28 39.29,35.97 23.54,35.97 23.54,44.35 12.62,44.35 12.62,39.65 15.16,39.65 15.16,41.81 19.16,41.81 19.16,15.77 0.55,15.77 0.55,6.18 13.82,6.18 13.82,10.63 23.54,10.63 23.54,20.28
CS_DCB_H on TOP: 12.41,17.43 10.08,17.43 10.08,16.03 12.41,16.03
CS_DCB_H on TOP: 12.41,35.72 10.08,35.72 10.08,34.32 12.41,34.32
CS_DCB_H on TOP: 12.41,27.85 10.08,27.85 10.08,26.44 12.41,26.44
CS_DCB_H on BOTTOM: 12.36,16.03 12.36,44.35 8.87,44.35 8.87,39.27 5.38,39.27 5.38,16.03
PH_A on TOP: 13.11,17.64 13.11,18.4 10.41,18.4 10.41,19.7 12.41,19.7 12.41,20.23 9.82,20.23 9.82,22.89 1.7,22.89 1.7,17.64
PH_B on TOP: 13.11,28.05 13.11,28.81 10.41,28.81 10.41,30.11 12.41,30.11 12.41,30.65 7.28,30.65 7.28,27.71 1.7,27.71 1.7,23.14 9.82,23.14 9.82,28.05
PH_C on TOP: 13.11,35.92 13.11,36.69 10.41,36.69 10.41,37.99 12.41,37.99 12.41,38.52 6.78,38.52 6.78,33.55 1.7,33.55 1.7,27.97 7.03,27.97 7.03,30.95 9.82,30.95 9.82,35.92
VM on TOP: 10.6,18.74 10.6,19.5 13.29,19.5 15.09,21.3 18.9,21.3 18.9,16.03 16.43,16.03 16.43,10.08 18.25,10.08 18.25,9.77 13.83,9.77 13.83,9.41 12.68,9.41 12.68,13.01 13.89,13.01 13.89,18.14 13.29,18.74
VM on TOP: 10.6,37.02 10.6,37.79 13.24,37.79 15.41,39.96 15.41,41.55 18.9,41.55 18.9,35.84 14.55,35.84 13.37,37.02
VM on TOP: 10.6,29.15 10.6,29.91 13.24,29.91 15.04,31.71 18.9,31.71 18.9,27.27 15.39,27.27 13.51,29.15
VM on BOTTOM: 18.9,41.55 18.9,16.03 14.4,16.03 14.4,39.4 15.41,39.4 15.41,41.55
N24141092 on TOP: 10.78,14.38 6.78,14.38 6.78,10.57 10.78,10.57
N24147651 on TOP: 22.65,11.87 27.2,11.87 27.2,7.71 29.41,7.71 29.41,15.71 20.95,15.71 20.95,10.27 22.65,10.27

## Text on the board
BOTTOM: 2 OF 8 | SECONDARY SIDE
Board Geometry/Soldermask Bottom: 6 OF 8 | SECONDARY SOLDERMASK
Ref Des/Silkscreen Bottom: 700-XXXXX | SCH-XXXXX | 8 OF 8 | SECONDARY SILKSCREEN
User.Comments: 1 OF 1 | TEST PROBE | 1/1 | 1
TOP: 1 OF 8 | PRIMARY SIDE
Board Geometry/Soldermask Top: 3 OF 8 | PRIMARY SOLDERMASK
Ref Des/Silkscreen Top: 5V | GND | ENCA | ENCB | ENCI | PHC | PHB | PHA | 5 OF 8 | PRIMARY SILKSCREEN | PWR | FRDM-MC-LVBLDC
DIMENSION: THICK +/- 10% | GRID ORIGIN | PRIMARY DATUM
BODY_CENTER: 22. DO NOT PROVIDE SOLDERMASK CLEARANCES FOR THE SPECIFIC LOCATIONS | LEAVE SOLDERMASK AS THEY APPEAR ON CAD. | 16 | 17 | 8
PASTEMASK_TOP: 4 OF 8 | PASTEMASK TOP
User.5: 7 OF 8 | SECONDARY PASTEMASK
User.17: FRDM-MC-LVBLDC
User.21: FIGURE | SIZE | 12.0 | 30.0 | 40.0 | 42.0 | 52.0 | 125.0 | 63.0x40.0 | DRILL CHART: TOP to BOTTOM | ALL UNITS ARE IN MILS | TOLERANCE | +2.0/-12.0 | +3.0/-3.0 | +2.0/-2.0 | PLATED | NON-PLATED | QTY | 160 | 6 | 5 | 64 | 3 | 4 | 2 | 1
